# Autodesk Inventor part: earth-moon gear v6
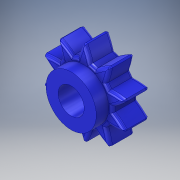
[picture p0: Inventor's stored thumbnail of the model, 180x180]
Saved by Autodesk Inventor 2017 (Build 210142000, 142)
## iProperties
Created: 2016-08
Part Number: earth-moon gear v6
Material: Generic
Document SubType Name: Modeling
Designer: Stan
Density: 1 g/cm^3
Appearance: Blue - Wall Paint - Glossy
Author: Stan
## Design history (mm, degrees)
sketch "Sketch3"
  geometry: A1 r 7.352 centre (0, 0) between (-5.527, 4.848) and (-6.319, 3.758); A2 r 7.352 centre (0, 0) between (-7.321, 0.674) and (-7.321, -0.674); A3 r 7.352 centre (0, 0) between (-6.319, -3.758) and (-5.527, -4.848); A4 r 7.352 centre (0, 0) between (-2.903, -6.755) and (-1.622, -7.171); A5 r 7.352 centre (0, 0) between (1.622, -7.171) and (2.903, -6.755); A6 r 7.352 centre (0, 0) between (5.527, -4.848) and (6.319, -3.758); A7 r 7.352 centre (0, 0) between (7.321, -0.674) and (7.321, 0.674); A8 r 7.352 centre (0, 0) between (6.319, 3.758) and (5.527, 4.848); A9 r 7.352 centre (0, 0) between (2.903, 6.755) and (1.622, 7.171); A10 r 7.352 centre (0, 0) between (-1.622, 7.171) and (-2.903, 6.755); A11 r 15.259 centre (13.156, 3.37) between (-0.246, 10.665) and (-1.622, 7.171); A12 r 15.259 centre (-13.156, 3.37) between (1.622, 7.171) and (0.246, 10.665); A13 r 15.259 centre (8.663, 10.459) between (-6.468, 8.484) and (-5.527, 4.848); A14 r 15.259 centre (-12.624, -5.007) between (-2.903, 6.755) and (-6.07, 8.773); A15 r 15.259 centre (0.861, 13.554) between (-10.219, 3.062) and (-7.321, 0.674); A16 r 15.259 centre (-7.27, -11.471) between (-6.319, 3.758) and (-10.067, 3.53); A17 r 15.259 centre (-7.27, 11.471) between (-10.067, -3.53) and (-6.319, -3.758); A18 r 15.259 centre (0.861, -13.554) between (-7.321, -0.674) and (-10.219, -3.062); A19 r 15.259 centre (-12.624, 5.007) between (-6.07, -8.773) and (-2.903, -6.755); A20 r 15.259 centre (8.663, -10.459) between (-5.527, -4.848) and (-6.468, -8.484); A21 r 15.259 centre (-13.156, -3.37) between (0.246, -10.665) and (1.622, -7.171); A22 r 15.259 centre (13.156, -3.37) between (-1.622, -7.171) and (-0.246, -10.665); A23 r 15.259 centre (-8.663, -10.459) between (6.468, -8.484) and (5.527, -4.848); A24 r 15.259 centre (12.624, 5.007) between (2.903, -6.755) and (6.07, -8.773); A25 r 15.259 centre (-0.861, -13.554) between (10.219, -3.062) and (7.321, -0.674); A26 r 15.259 centre (7.27, 11.471) between (6.319, -3.758) and (10.067, -3.53); A27 r 15.259 centre (7.27, -11.471) between (10.067, 3.53) and (6.319, 3.758); A28 r 15.259 centre (-0.861, 13.554) between (7.321, 0.674) and (10.219, 3.062); A29 r 15.259 centre (12.624, -5.007) between (6.07, 8.773) and (2.903, 6.755); A30 r 15.259 centre (-8.663, 10.459) between (5.527, 4.848) and (6.468, 8.484); A31 r 10.668 centre (0, 0) between (-0.246, -10.665) and (0.246, -10.665); A32 r 10.668 centre (0, 0) between (6.07, -8.773) and (6.468, -8.484); A33 r 10.668 centre (0, 0) between (10.067, -3.53) and (10.219, -3.062); A34 r 10.668 centre (0, 0) between (10.219, 3.062) and (10.067, 3.53); A35 r 10.668 centre (0, 0) between (6.468, 8.484) and (6.07, 8.773); A36 r 10.668 centre (0, 0) between (0.246, 10.665) and (-0.246, 10.665); A37 r 10.668 centre (0, 0) between (-6.07, 8.773) and (-6.468, 8.484); A38 r 10.668 centre (0, 0) between (-10.067, 3.53) and (-10.219, 3.062); A39 r 10.668 centre (0, 0) between (-10.219, -3.062) and (-10.067, -3.53); A40 r 10.668 centre (0, 0) between (-6.468, -8.484) and (-6.07, -8.773); 11 further points
  constraints: 90 point on circle, 40 centre point, 1 coincident
extrude "Extrusion3" new body sketch "Sketch3" distance "d17" = 6.35; taper "d18" = 0 deg
sketch "Sketch4"
  geometry: C1 r 6.35 at (0, 0); 1 further point
  constraints: 1 centre point, 1 coincident
  dimensions: "d19" = 12.7 diameter of C1
extrude "Extrusion4" join sketch "Sketch4" distance "d20" = 3.175; taper "d21" = 0 deg
sketch "Sketch5"
  geometry: C1 r 3.302 at (0, 0); 1 further point
  constraints: 1 centre point, 1 coincident
  dimensions: "d22" = 6.604 diameter of C1
extrude "Extrusion5" cut sketch "Sketch5" distance "d23" = 9.525; taper "d24" = 0 deg
fillet "Fillet8" dims "d28" = 0.79375
fillet "Fillet9" dims "d29" = 0.79375
body "Solid2"
